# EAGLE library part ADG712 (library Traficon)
Quad SPST analog switches Normal Open
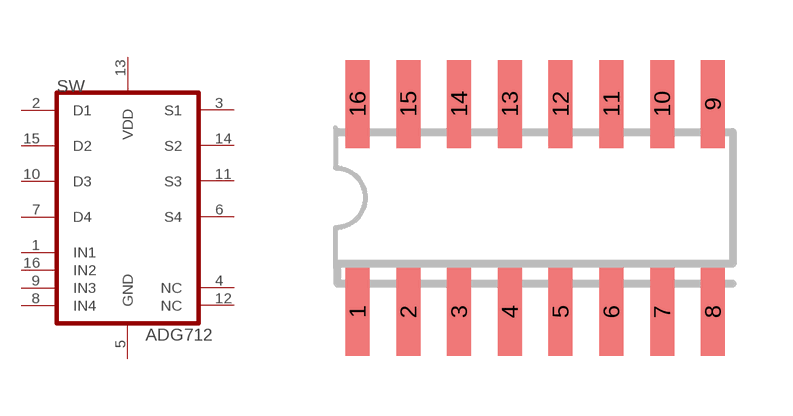
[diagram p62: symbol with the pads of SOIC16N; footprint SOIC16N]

Designator prefix SW

## ADG712BRZ  [SOIC16N]
1  IN1
2  D1
3  S1
4  NC  nc
5  GND
6  S4
7  D4
8  IN4
9  IN3
10  D3
11  S3
12  NC  nc
13  VDD
14  S2
15  D2
16  IN2

## Footprint SOIC16N (pad centres in mm)
SMALL OUTLINE INTEGRATED CIRCUIT
smd 0.6 x 2.2: 1 -4.445,-2.6; 2 -3.175,-2.6; 3 -1.905,-2.6; 4 -0.635,-2.6; 5 0.635,-2.6; 6 1.905,-2.6; 7 3.175,-2.6; 8 4.445,-2.6; 9 4.445,2.6; 10 3.175,2.6; 11 1.905,2.6; 12 0.635,2.6; 13 -0.635,2.6; 14 -1.905,2.6; 15 -3.175,2.6; 16 -4.445,2.6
